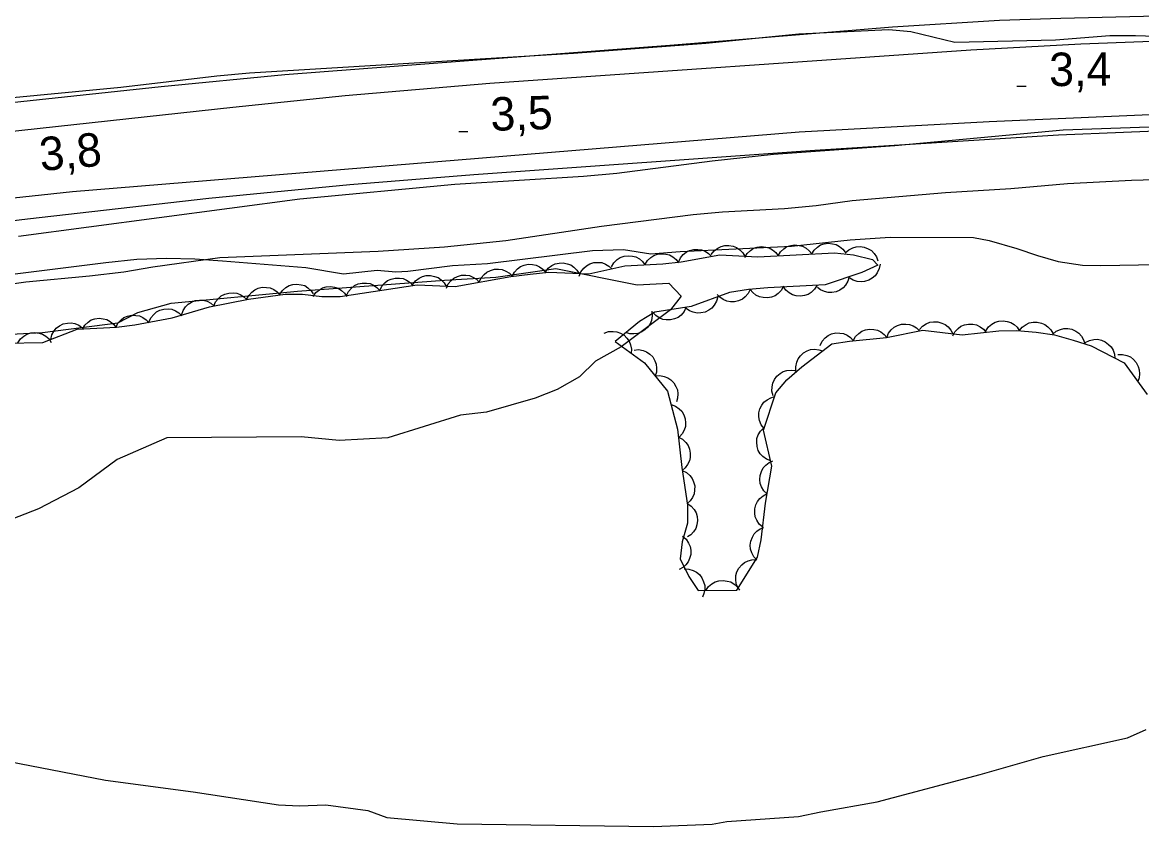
# Model space of a CAD drawing. Extents: x 336540 to 340074, y 5572036 to 5573747.
# Drawn here: x 337457 to 337557.3, y 5572527.9 to 5572600 of the extents above; entities that cross this region are included whole.
import ezdxf

# ---------------------------------------------------------------- set-up
doc = ezdxf.new("R2010")
doc.units = 0
for name, color, linetype in [('Niveau 2', 7, 'Continuous'), ('Niveau 21', 7, 'Continuous'), ('Niveau 22', 7, 'Continuous'), ('Niveau 3', 7, 'Continuous'), ('Niveau 44', 7, 'Continuous')]:
    doc.layers.add(name, color=color, linetype=linetype)

msp = doc.modelspace()

# ---------------------------------------------------------------- linework, layer by layer
at = {"layer": 'Niveau 2'}
for points in [[(337454.29, 5572593.07), (337465.88, 5572594.2), (337474.46, 5572595.21), (337477.38, 5572595.48), (337506.41, 5572597.24), (337518.28, 5572598.13), (337526.61, 5572598.97), (337534.67, 5572599.35), (337536.64, 5572599.18), (337540.58, 5572598.21), (337549.58, 5572598.43), (337554.45, 5572598.83), (337556.75, 5572598.82), (337564.94, 5572598.55)], [(337578.28, 5572592.63), (337576.34, 5572592.13), (337574.79, 5572591.92), (337569.28, 5572591.48), (337566.31, 5572591.08), (337563.11, 5572590.77), (337550.27, 5572590.34), (337535.19, 5572588.94), (337524.33, 5572588.14), (337518.83, 5572587.55), (337510.3, 5572586.46), (337507.3, 5572586.18), (337495.8, 5572585.47), (337481.91, 5572584.15), (337456.71, 5572580.8)], [(337455.69, 5572577.37), (337464.51, 5572578.48), (337467.29, 5572578.76), (337469.97, 5572578.86), (337472.51, 5572578.79), (337474.98, 5572578.62), (337482.45, 5572578.03), (337485.82, 5572577.46), (337488.82, 5572577.78), (337490.49, 5572577.64), (337491.58, 5572577.71), (337495.58, 5572578.2), (337498.71, 5572578.39), (337508.12, 5572579.55), (337510.88, 5572579.63), (337513.33, 5572579.24), (337515.97, 5572579.45), (337525.94, 5572579.95), (337531.21, 5572580.52), (337534.79, 5572580.76), (337542.25, 5572580.73), (337543.66, 5572580.44), (337546.14, 5572579.74), (337547.98, 5572579.09), (337549.83, 5572578.57), (337552.01, 5572578.25), (337553.64, 5572578.2), (337558.74, 5572578.3)], [(337444.67, 5572571.46), (337458.85, 5572572.19), (337465.59, 5572573.06), (337467.39, 5572573.99), (337470.39, 5572574.82), (337481.68, 5572575.91), (337494.87, 5572576.9), (337499.46, 5572577.17), (337504.82, 5572577.95), (337512.11, 5572576.46), (337514.96, 5572576.61), (337516.05, 5572575.46)], [(337516.05, 5572575.46), (337515.09, 5572574.22), (337510.68, 5572570.93), (337508.38, 5572569.63), (337506.94, 5572568.22), (337504.96, 5572567.08), (337502.99, 5572566.33), (337498.63, 5572565.07), (337496.28, 5572564.78), (337489.78, 5572562.75), (337485.42, 5572562.53), (337482.01, 5572562.86), (337470, 5572562.76), (337465.53, 5572560.83), (337462.12, 5572558.28), (337458.48, 5572556.39), (337455.5, 5572555.23), (337451.99, 5572554.54), (337449.35, 5572553.22), (337440.82, 5572551.25), (337435.3, 5572549.68)]]:
    msp.add_lwpolyline(points, dxfattribs=at)
at = {"layer": 'Niveau 21'}
for points in [[(337420.85, 5572589.04), (337469.47, 5572594.26), (337480.57, 5572595.33), (337515.42, 5572597.98), (337535, 5572599.61), (337544.58, 5572600.19), (337550.06, 5572600.38), (337598.2, 5572601.54), (337614.52, 5572601.61), (337655.5, 5572601.49), (337679.62, 5572601.06), (337710.85, 5572600.68), (337716.59, 5572600.49), (337723.21, 5572600.45), (337730.46, 5572600.17), (337746.92, 5572599.86)], [(337742.17, 5572598.21), (337711.32, 5572598.36), (337677.31, 5572598.73), (337652.3, 5572599.16), (337611.58, 5572599.51), (337600.96, 5572599.42), (337574.84, 5572598.81), (337564.55, 5572598.53), (337551.87, 5572598.05), (337542.02, 5572597.49), (337498.93, 5572594.53), (337485.96, 5572593.4), (337475.89, 5572592.36), (337426.83, 5572587.03)], [(337352.94, 5572571.52), (337383.95, 5572575.87), (337413.72, 5572579.71), (337461.55, 5572584.84), (337526.62, 5572590.2), (337543.66, 5572591.12), (337577.94, 5572592.61), (337610.08, 5572593.14), (337670.84, 5572592.4), (337698.78, 5572591.75), (337718.4, 5572591.92), (337765.14, 5572590.89)], [(337443.52, 5572580.72), (337457.51, 5572582.4), (337473.74, 5572584.23), (337486.38, 5572585.46), (337497.48, 5572586.37), (337528.02, 5572588.55), (337549.85, 5572589.91), (337567.34, 5572590.63), (337583.41, 5572591.15), (337595.91, 5572591.37), (337605.15, 5572591.37), (337627.52, 5572590.98), (337656.05, 5572590.97), (337680.34, 5572590.56), (337711.5, 5572590.18), (337758.99, 5572589.08)]]:
    msp.add_lwpolyline(points, dxfattribs=at)
at = {"layer": 'Niveau 22'}
for points in [[(337451.66, 5572575.93), (337457.35, 5572576.75), (337463.05, 5572577.28), (337466.15, 5572577.65), (337468.74, 5572578.1), (337474.75, 5572578.92), (337488.93, 5572579.49), (337494.87, 5572579.89), (337500.36, 5572580.44), (337508.91, 5572581.72), (337517.14, 5572582.77), (337519.77, 5572583.01), (337525.31, 5572583.3), (337528.15, 5572583.59), (337531.39, 5572584.04), (337539.74, 5572584.74), (337545.6, 5572585.12), (337550.67, 5572585.57), (337556.4, 5572585.86), (337562.73, 5572586.03)], [(337448.13, 5572535.26), (337464.5, 5572532.08), (337472.35, 5572531.05), (337480, 5572529.86), (337481.87, 5572529.78), (337484.23, 5572529.88), (337487.98, 5572529.36), (337489.69, 5572528.75), (337495.99, 5572528.18), (337513.58, 5572527.92), (337518.83, 5572528.15), (337520.16, 5572528.38), (337526.58, 5572528.82), (337528.58, 5572529.25), (337533.62, 5572530.15), (337542.83, 5572532.58), (337548.5, 5572534.2), (337556.04, 5572535.87), (337557.72, 5572536.62)]]:
    msp.add_lwpolyline(points, dxfattribs=at)
at = {"layer": 'Niveau 3'}
for p, q in [((337546.14, 5572594.28), (337546.95, 5572594.29)), ((337496.13, 5572590.22), (337496.94, 5572590.23))]:
    msp.add_line(p, q, dxfattribs=at)
at = {"layer": 'Niveau 44'}
for points in [[(337518.76, 5572579.19), (337519.01, 5572579.52), (337519.34, 5572579.76), (337519.63, 5572579.92), (337519.97, 5572579.99), (337520.34, 5572580.01), (337520.71, 5572579.93), (337521.02, 5572579.82), (337521.31, 5572579.62), (337521.57, 5572579.35), (337521.76, 5572579.05)], [(337524.75, 5572579.08), (337524.97, 5572579.44), (337525.27, 5572579.71), (337525.54, 5572579.9), (337525.88, 5572580.01), (337526.25, 5572580.06), (337526.63, 5572580.01), (337526.94, 5572579.94), (337527.25, 5572579.76), (337527.53, 5572579.52), (337527.75, 5572579.24)], [(337527.75, 5572579.24), (337527.96, 5572579.59), (337528.27, 5572579.86), (337528.54, 5572580.05), (337528.88, 5572580.16), (337529.24, 5572580.21), (337529.62, 5572580.16), (337529.94, 5572580.09), (337530.24, 5572579.91), (337530.53, 5572579.68), (337530.74, 5572579.39)], [(337452.1, 5572571.2), (337458.89, 5572571.31), (337461.97, 5572572.49), (337465.48, 5572572.67), (337467.13, 5572572.89), (337470.46, 5572573.53), (337473.82, 5572574.49), (337477.3, 5572575.18), (337480.58, 5572575.64), (337482.13, 5572575.65), (337483.86, 5572575.43), (337485.51, 5572575.43), (337492.4, 5572576.47), (337495.81, 5572576.31), (337500.8, 5572577.23), (337502.54, 5572577.44), (337504.21, 5572577.61), (337507.79, 5572577.45), (337511.02, 5572578.17), (337514.41, 5572578.37), (337516.06, 5572578.55), (337519.52, 5572579.15), (337522.93, 5572578.99), (337529.8, 5572579.34), (337531.49, 5572579.16), (337533.19, 5572578.75), (337533.69, 5572578.25), (337532.24, 5572577.58), (337528.96, 5572576.47), (337523.83, 5572576.21), (337522.08, 5572576.05), (337520.38, 5572575.79), (337516.97, 5572574.53), (337513.69, 5572574.01), (337512.32, 5572573.19), (337510.16, 5572571.41), (337512.77, 5572569.49), (337514.85, 5572566.94), (337515.74, 5572563.54), (337516.12, 5572560.11), (337516.62, 5572556.72), (337516.62, 5572555.13), (337516.14, 5572553.45), (337515.98, 5572551.92), (337516.76, 5572550.35), (337517.59, 5572549.07), (337521.05, 5572549.11), (337522.91, 5572552.08), (337523.24, 5572553.61), (337523.62, 5572556.92), (337524.18, 5572560.23), (337523.44, 5572563.46), (337524.53, 5572566.79), (337525.54, 5572567.97), (337526.86, 5572569.12), (337529.57, 5572571.2), (337531.13, 5572571.44), (337534.45, 5572571.74), (337537.71, 5572572.42), (337541.23, 5572571.99), (337544.52, 5572572.36), (337546.12, 5572572.37), (337547.87, 5572572.24), (337549.5, 5572572), (337551.18, 5572571.52), (337552.79, 5572571.02), (337555.73, 5572569.47), (337557.81, 5572566.65)], [(337509.83, 5572578.1), (337510.04, 5572578.46), (337510.34, 5572578.73), (337510.61, 5572578.92), (337510.95, 5572579.03), (337511.31, 5572579.08), (337511.69, 5572579.04), (337512.01, 5572578.97), (337512.32, 5572578.8), (337512.6, 5572578.56), (337512.82, 5572578.28)], [(337512.82, 5572578.28), (337513.04, 5572578.64), (337513.34, 5572578.91), (337513.61, 5572579.1), (337513.94, 5572579.21), (337514.31, 5572579.26), (337514.69, 5572579.22), (337515.01, 5572579.15), (337515.31, 5572578.97), (337515.6, 5572578.74), (337515.82, 5572578.45)], [(337515.81, 5572578.51), (337515.99, 5572578.89), (337516.25, 5572579.19), (337516.5, 5572579.41), (337516.82, 5572579.56), (337517.18, 5572579.65), (337517.56, 5572579.65), (337517.89, 5572579.62), (337518.21, 5572579.48), (337518.52, 5572579.28), (337518.77, 5572579.02)], [(337521.76, 5572578.93), (337521.97, 5572579.29), (337522.28, 5572579.56), (337522.55, 5572579.75), (337522.88, 5572579.85), (337523.25, 5572579.9), (337523.63, 5572579.86), (337523.95, 5572579.79), (337524.25, 5572579.61), (337524.54, 5572579.37), (337524.75, 5572579.08)], [(337530.76, 5572579.34), (337531.07, 5572579.62), (337531.43, 5572579.79), (337531.75, 5572579.89), (337532.1, 5572579.9), (337532.46, 5572579.85), (337532.82, 5572579.7), (337533.1, 5572579.54), (337533.34, 5572579.28), (337533.55, 5572578.97), (337533.67, 5572578.63)], [(337500.93, 5572577.25), (337501.12, 5572577.62), (337501.4, 5572577.91), (337501.66, 5572578.11), (337501.99, 5572578.24), (337502.35, 5572578.32), (337502.73, 5572578.3), (337503.06, 5572578.25), (337503.37, 5572578.09), (337503.67, 5572577.88), (337503.91, 5572577.61)], [(337503.91, 5572577.62), (337504.16, 5572577.96), (337504.49, 5572578.2), (337504.78, 5572578.36), (337505.12, 5572578.43), (337505.49, 5572578.45), (337505.86, 5572578.37), (337506.17, 5572578.27), (337506.46, 5572578.06), (337506.72, 5572577.8), (337506.91, 5572577.49)], [(337506.93, 5572577.26), (337507.08, 5572577.65), (337507.33, 5572577.96), (337507.57, 5572578.19), (337507.88, 5572578.36), (337508.23, 5572578.47), (337508.62, 5572578.49), (337508.94, 5572578.47), (337509.27, 5572578.34), (337509.59, 5572578.16), (337509.85, 5572577.91)], [(337533.88, 5572578.34), (337533.81, 5572577.93), (337533.63, 5572577.56), (337533.45, 5572577.29), (337533.18, 5572577.06), (337532.86, 5572576.88), (337532.49, 5572576.78), (337532.17, 5572576.73), (337531.82, 5572576.78), (337531.46, 5572576.89), (337531.16, 5572577.08)], [(337489.06, 5572575.97), (337489.24, 5572576.34), (337489.51, 5572576.64), (337489.76, 5572576.85), (337490.09, 5572576.99), (337490.45, 5572577.08), (337490.83, 5572577.07), (337491.15, 5572577.03), (337491.47, 5572576.89), (337491.78, 5572576.68), (337492.02, 5572576.41)], [(337492.02, 5572576.49), (337492.27, 5572576.82), (337492.6, 5572577.06), (337492.89, 5572577.22), (337493.23, 5572577.3), (337493.6, 5572577.31), (337493.97, 5572577.23), (337494.28, 5572577.13), (337494.57, 5572576.92), (337494.83, 5572576.65), (337495.02, 5572576.35)], [(337495.03, 5572576.17), (337495.19, 5572576.55), (337495.46, 5572576.86), (337495.71, 5572577.08), (337496.02, 5572577.23), (337496.38, 5572577.33), (337496.76, 5572577.33), (337497.09, 5572577.3), (337497.41, 5572577.16), (337497.73, 5572576.97), (337497.98, 5572576.71)], [(337497.98, 5572576.71), (337498.15, 5572577.09), (337498.41, 5572577.4), (337498.66, 5572577.62), (337498.97, 5572577.77), (337499.33, 5572577.87), (337499.71, 5572577.88), (337500.04, 5572577.85), (337500.36, 5572577.71), (337500.68, 5572577.51), (337500.93, 5572577.25)], [(337531.11, 5572577.2), (337531, 5572576.79), (337530.78, 5572576.45), (337530.57, 5572576.2), (337530.28, 5572576), (337529.94, 5572575.86), (337529.56, 5572575.79), (337529.23, 5572575.78), (337528.89, 5572575.87), (337528.55, 5572576.02), (337528.27, 5572576.24)], [(337477.14, 5572575.16), (337477.33, 5572575.53), (337477.6, 5572575.83), (337477.86, 5572576.04), (337478.18, 5572576.18), (337478.54, 5572576.26), (337478.93, 5572576.25), (337479.25, 5572576.2), (337479.57, 5572576.05), (337479.87, 5572575.84), (337480.11, 5572575.57)], [(337480.11, 5572575.64), (337480.34, 5572575.98), (337480.66, 5572576.24), (337480.94, 5572576.42), (337481.28, 5572576.51), (337481.64, 5572576.54), (337482.02, 5572576.48), (337482.34, 5572576.4), (337482.63, 5572576.2), (337482.91, 5572575.95), (337483.11, 5572575.66)], [(337483.1, 5572575.43), (337483.33, 5572575.78), (337483.65, 5572576.03), (337483.93, 5572576.2), (337484.27, 5572576.29), (337484.64, 5572576.33), (337485.01, 5572576.26), (337485.33, 5572576.17), (337485.62, 5572575.98), (337485.89, 5572575.73), (337486.1, 5572575.43)], [(337486.09, 5572575.52), (337486.27, 5572575.89), (337486.54, 5572576.19), (337486.8, 5572576.41), (337487.12, 5572576.55), (337487.48, 5572576.63), (337487.86, 5572576.63), (337488.19, 5572576.59), (337488.51, 5572576.44), (337488.81, 5572576.23), (337489.06, 5572575.97)], [(337522.24, 5572576.07), (337522.06, 5572575.7), (337521.79, 5572575.4), (337521.54, 5572575.18), (337521.21, 5572575.04), (337520.85, 5572574.96), (337520.47, 5572574.96), (337520.15, 5572575), (337519.83, 5572575.15), (337519.52, 5572575.36), (337519.28, 5572575.62)], [(337525.23, 5572576.34), (337525.03, 5572575.97), (337524.74, 5572575.69), (337524.47, 5572575.49), (337524.14, 5572575.37), (337523.78, 5572575.31), (337523.4, 5572575.33), (337523.08, 5572575.39), (337522.76, 5572575.56), (337522.47, 5572575.79), (337522.24, 5572576.06)], [(337528.23, 5572576.43), (337528.01, 5572576.08), (337527.71, 5572575.8), (337527.44, 5572575.62), (337527.1, 5572575.51), (337526.74, 5572575.46), (337526.36, 5572575.5), (337526.04, 5572575.58), (337525.74, 5572575.76), (337525.45, 5572575.99), (337525.23, 5572576.28)], [(337471.31, 5572573.77), (337471.44, 5572574.17), (337471.67, 5572574.5), (337471.9, 5572574.75), (337472.2, 5572574.93), (337472.54, 5572575.06), (337472.93, 5572575.1), (337473.25, 5572575.1), (337473.59, 5572575), (337473.92, 5572574.83), (337474.19, 5572574.6)], [(337474.2, 5572574.57), (337474.36, 5572574.95), (337474.62, 5572575.26), (337474.87, 5572575.49), (337475.18, 5572575.64), (337475.54, 5572575.74), (337475.92, 5572575.75), (337476.25, 5572575.73), (337476.57, 5572575.6), (337476.89, 5572575.4), (337477.15, 5572575.15)], [(337519.33, 5572575.4), (337519.23, 5572575), (337519.02, 5572574.65), (337518.82, 5572574.39), (337518.53, 5572574.19), (337518.2, 5572574.03), (337517.82, 5572573.96), (337517.5, 5572573.93), (337517.15, 5572574.01), (337516.81, 5572574.15), (337516.52, 5572574.36)], [(337468.38, 5572573.13), (337468.55, 5572573.51), (337468.81, 5572573.83), (337469.05, 5572574.05), (337469.37, 5572574.2), (337469.73, 5572574.3), (337470.11, 5572574.31), (337470.43, 5572574.28), (337470.76, 5572574.15), (337471.07, 5572573.95), (337471.33, 5572573.7)], [(337513.43, 5572574.1), (337513.47, 5572573.69), (337513.39, 5572573.29), (337513.28, 5572572.98), (337513.07, 5572572.69), (337512.81, 5572572.43), (337512.48, 5572572.24), (337512.18, 5572572.11), (337511.83, 5572572.07), (337511.46, 5572572.09), (337511.11, 5572572.2)], [(337516.49, 5572574.45), (337516.32, 5572574.08), (337516.05, 5572573.77), (337515.79, 5572573.56), (337515.47, 5572573.42), (337515.11, 5572573.33), (337514.73, 5572573.33), (337514.41, 5572573.37), (337514.09, 5572573.52), (337513.78, 5572573.72), (337513.53, 5572573.98)], [(337459.59, 5572571.58), (337459.69, 5572571.99), (337459.89, 5572572.34), (337460.09, 5572572.6), (337460.38, 5572572.81), (337460.71, 5572572.97), (337461.09, 5572573.04), (337461.41, 5572573.07), (337461.76, 5572573), (337462.1, 5572572.86), (337462.39, 5572572.65)], [(337462.42, 5572572.51), (337462.64, 5572572.87), (337462.94, 5572573.14), (337463.22, 5572573.33), (337463.55, 5572573.44), (337463.92, 5572573.49), (337464.3, 5572573.44), (337464.61, 5572573.37), (337464.92, 5572573.19), (337465.2, 5572572.95), (337465.42, 5572572.67)], [(337465.42, 5572572.66), (337465.61, 5572573.04), (337465.89, 5572573.33), (337466.14, 5572573.54), (337466.47, 5572573.67), (337466.83, 5572573.75), (337467.21, 5572573.74), (337467.53, 5572573.69), (337467.85, 5572573.54), (337468.15, 5572573.33), (337468.39, 5572573.06)], [(337534.47, 5572571.74), (337534.63, 5572572.13), (337534.88, 5572572.45), (337535.13, 5572572.67), (337535.44, 5572572.83), (337535.79, 5572572.94), (337536.18, 5572572.95), (337536.5, 5572572.93), (337536.83, 5572572.8), (337537.15, 5572572.61), (337537.41, 5572572.36)], [(337537.4, 5572572.46), (337537.68, 5572572.77), (337538.02, 5572572.99), (337538.32, 5572573.13), (337538.67, 5572573.17), (337539.04, 5572573.16), (337539.41, 5572573.05), (337539.71, 5572572.93), (337539.98, 5572572.7), (337540.22, 5572572.41), (337540.38, 5572572.09)], [(337540.38, 5572571.89), (337540.57, 5572572.26), (337540.86, 5572572.55), (337541.12, 5572572.76), (337541.45, 5572572.88), (337541.81, 5572572.96), (337542.19, 5572572.94), (337542.51, 5572572.88), (337542.83, 5572572.72), (337543.13, 5572572.5), (337543.36, 5572572.23)], [(337543.35, 5572572.35), (337543.58, 5572572.7), (337543.9, 5572572.96), (337544.18, 5572573.13), (337544.52, 5572573.22), (337544.89, 5572573.26), (337545.27, 5572573.2), (337545.58, 5572573.11), (337545.88, 5572572.92), (337546.15, 5572572.67), (337546.35, 5572572.37)], [(337546.35, 5572572.35), (337546.61, 5572572.68), (337546.95, 5572572.91), (337547.24, 5572573.06), (337547.58, 5572573.13), (337547.95, 5572573.13), (337548.33, 5572573.04), (337548.63, 5572572.93), (337548.91, 5572572.71), (337549.16, 5572572.44), (337549.34, 5572572.13)], [(337456.64, 5572571.27), (337456.87, 5572571.62), (337457.18, 5572571.88), (337457.46, 5572572.06), (337457.8, 5572572.16), (337458.17, 5572572.19), (337458.55, 5572572.14), (337458.86, 5572572.05), (337459.16, 5572571.86), (337459.44, 5572571.62), (337459.64, 5572571.32)], [(337509.17, 5572572.14), (337509.56, 5572572.28), (337509.97, 5572572.3), (337510.29, 5572572.27), (337510.62, 5572572.14), (337510.94, 5572571.95), (337511.2, 5572571.68), (337511.4, 5572571.42), (337511.53, 5572571.09), (337511.6, 5572570.72), (337511.58, 5572570.36)], [(337528.51, 5572571.04), (337528.69, 5572571.42), (337528.97, 5572571.72), (337529.22, 5572571.93), (337529.54, 5572572.07), (337529.9, 5572572.16), (337530.28, 5572572.15), (337530.61, 5572572.11), (337530.93, 5572571.97), (337531.23, 5572571.76), (337531.48, 5572571.49)], [(337531.48, 5572571.47), (337531.68, 5572571.84), (337531.98, 5572572.12), (337532.24, 5572572.32), (337532.57, 5572572.44), (337532.94, 5572572.5), (337533.32, 5572572.47), (337533.64, 5572572.41), (337533.95, 5572572.25), (337534.24, 5572572.02), (337534.47, 5572571.74)], [(337549.34, 5572572.05), (337549.66, 5572572.32), (337550.03, 5572572.47), (337550.35, 5572572.56), (337550.7, 5572572.56), (337551.06, 5572572.49), (337551.41, 5572572.32), (337551.69, 5572572.15), (337551.92, 5572571.88), (337552.11, 5572571.56), (337552.22, 5572571.22)], [(337552.26, 5572571.3), (337552.63, 5572571.5), (337553.02, 5572571.58), (337553.35, 5572571.6), (337553.7, 5572571.52), (337554.04, 5572571.38), (337554.34, 5572571.14), (337554.58, 5572570.92), (337554.75, 5572570.61), (337554.87, 5572570.26), (337554.91, 5572569.9)], [(337511.84, 5572570.63), (337512.25, 5572570.67), (337512.65, 5572570.59), (337512.96, 5572570.48), (337513.25, 5572570.27), (337513.51, 5572570.01), (337513.69, 5572569.67), (337513.83, 5572569.37), (337513.86, 5572569.02), (337513.84, 5572568.65), (337513.73, 5572568.31)], [(337526.34, 5572568.72), (337526.32, 5572569.14), (337526.41, 5572569.54), (337526.53, 5572569.84), (337526.75, 5572570.12), (337527.02, 5572570.37), (337527.36, 5572570.55), (337527.66, 5572570.67), (337528.01, 5572570.7), (337528.38, 5572570.66), (337528.72, 5572570.55)], [(337555.18, 5572570.22), (337555.6, 5572570.23), (337555.99, 5572570.13), (337556.3, 5572570.01), (337556.57, 5572569.79), (337556.82, 5572569.51), (337556.99, 5572569.17), (337557.1, 5572568.86), (337557.12, 5572568.51), (337557.08, 5572568.14), (337556.96, 5572567.8)], [(337513.73, 5572568.31), (337514.15, 5572568.35), (337514.55, 5572568.26), (337514.86, 5572568.15), (337515.14, 5572567.95), (337515.4, 5572567.68), (337515.59, 5572567.35), (337515.72, 5572567.05), (337515.76, 5572566.7), (337515.73, 5572566.33), (337515.63, 5572565.98)], [(337524.3, 5572566.53), (337524.19, 5572566.93), (337524.2, 5572567.33), (337524.26, 5572567.66), (337524.41, 5572567.98), (337524.62, 5572568.28), (337524.92, 5572568.52), (337525.19, 5572568.7), (337525.53, 5572568.8), (337525.9, 5572568.84), (337526.25, 5572568.8)], [(337523.49, 5572563.61), (337523.23, 5572563.94), (337523.09, 5572564.32), (337523.01, 5572564.64), (337523.03, 5572564.99), (337523.12, 5572565.35), (337523.29, 5572565.69), (337523.48, 5572565.96), (337523.75, 5572566.18), (337524.08, 5572566.36), (337524.42, 5572566.46)], [(337515.16, 5572565.75), (337515.56, 5572565.61), (337515.88, 5572565.37), (337516.12, 5572565.14), (337516.3, 5572564.83), (337516.42, 5572564.48), (337516.45, 5572564.1), (337516.45, 5572563.78), (337516.33, 5572563.44), (337516.16, 5572563.11), (337515.92, 5572562.84)], [(337524.08, 5572560.69), (337523.69, 5572560.84), (337523.37, 5572561.09), (337523.13, 5572561.33), (337522.97, 5572561.64), (337522.86, 5572561.99), (337522.84, 5572562.37), (337522.85, 5572562.7), (337522.97, 5572563.03), (337523.16, 5572563.35), (337523.41, 5572563.61)], [(337515.82, 5572562.82), (337516.19, 5572562.63), (337516.48, 5572562.34), (337516.68, 5572562.08), (337516.81, 5572561.75), (337516.88, 5572561.39), (337516.86, 5572561.01), (337516.8, 5572560.69), (337516.64, 5572560.37), (337516.42, 5572560.08), (337516.15, 5572559.84)], [(337523.76, 5572557.73), (337523.46, 5572558.02), (337523.26, 5572558.38), (337523.13, 5572558.68), (337523.1, 5572559.03), (337523.13, 5572559.4), (337523.26, 5572559.76), (337523.4, 5572560.06), (337523.64, 5572560.32), (337523.93, 5572560.54), (337524.26, 5572560.69)], [(337516.16, 5572559.84), (337516.54, 5572559.66), (337516.84, 5572559.39), (337517.05, 5572559.13), (337517.18, 5572558.81), (337517.27, 5572558.45), (337517.26, 5572558.07), (337517.22, 5572557.74), (337517.07, 5572557.43), (337516.86, 5572557.12), (337516.6, 5572556.88)], [(337516.62, 5572556.88), (337516.97, 5572556.64), (337517.22, 5572556.33), (337517.39, 5572556.05), (337517.48, 5572555.71), (337517.52, 5572555.34), (337517.45, 5572554.96), (337517.36, 5572554.65), (337517.17, 5572554.35), (337516.92, 5572554.08), (337516.62, 5572553.88)], [(337523.37, 5572554.76), (337523.06, 5572555.03), (337522.84, 5572555.38), (337522.7, 5572555.68), (337522.65, 5572556.02), (337522.66, 5572556.39), (337522.76, 5572556.76), (337522.89, 5572557.06), (337523.11, 5572557.33), (337523.4, 5572557.57), (337523.71, 5572557.74)], [(337516.19, 5572553.94), (337516.51, 5572553.67), (337516.73, 5572553.33), (337516.87, 5572553.03), (337516.93, 5572552.69), (337516.92, 5572552.32), (337516.82, 5572551.95), (337516.7, 5572551.65), (337516.48, 5572551.37), (337516.2, 5572551.13), (337515.88, 5572550.96)], [(337522.85, 5572551.81), (337522.56, 5572552.11), (337522.38, 5572552.47), (337522.27, 5572552.79), (337522.25, 5572553.14), (337522.3, 5572553.5), (337522.44, 5572553.86), (337522.59, 5572554.15), (337522.85, 5572554.39), (337523.15, 5572554.61), (337523.48, 5572554.74)], [(337516.33, 5572551.01), (337516.75, 5572551), (337517.14, 5572550.88), (337517.43, 5572550.73), (337517.69, 5572550.5), (337517.92, 5572550.21), (337518.07, 5572549.85), (337518.17, 5572549.54), (337518.17, 5572549.19), (337518.1, 5572548.82), (337517.96, 5572548.49)], [(337521.17, 5572549.3), (337521, 5572549.68), (337520.95, 5572550.09), (337520.96, 5572550.42), (337521.06, 5572550.75), (337521.23, 5572551.08), (337521.48, 5572551.37), (337521.72, 5572551.59), (337522.05, 5572551.74), (337522.4, 5572551.83), (337522.76, 5572551.85)], [(337518.28, 5572549.08), (337518.51, 5572549.43), (337518.82, 5572549.69), (337519.1, 5572549.86), (337519.44, 5572549.96), (337519.81, 5572549.99), (337520.19, 5572549.93), (337520.5, 5572549.85), (337520.8, 5572549.66), (337521.07, 5572549.41), (337521.28, 5572549.11)]]:
    msp.add_lwpolyline(points, dxfattribs=at)

# ---------------------------------------------------------------- texts
at = {"layer": 'Niveau 3'}
for s, rotation, p in [('3,4    ', 0.342, (337549.03, 5572594.28)), ('3,5    ', 1.7662, (337499.02, 5572590.27)), ('3,8    ', 5.0475, (337458.7, 5572586.67))]:
    msp.add_text(s, height=3, rotation=rotation, dxfattribs=at).set_placement(p)

doc.saveas('drawing.dxf')
